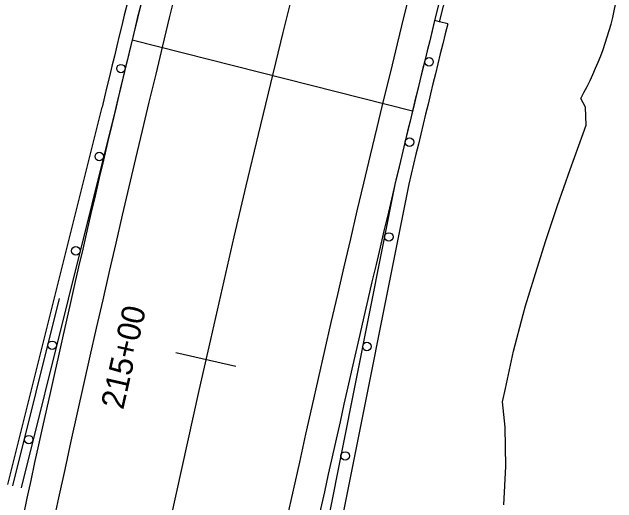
# Model space of a CAD drawing. Extents: x 1441466 to 1476381, y 2042742 to 2057194.
# Drawn here: x 1445767.1 to 1445924, y 2054420.2 to 2054547.4 of the extents above; entities that cross this region are included whole.
import ezdxf

# ---------------------------------------------------------------- set-up
doc = ezdxf.new("R2010")
doc.units = 0
for name, color, linetype in [('R_Bridge', 7, 'Continuous'), ('R_Guardrail', 7, 'Continuous'), ('R_Horz Alg', 7, 'Continuous'), ('R_Horz Alg Stationing', 7, 'Continuous'), ('R_Proposed Const Limits', 7, 'Continuous'), ('R_Proposed Road', 7, 'Continuous'), ('R_Shld', 7, 'Continuous')]:
    doc.layers.add(name, color=color, linetype=linetype)

msp = doc.modelspace()

# ---------------------------------------------------------------- linework, layer by layer
at = {"layer": 'R_Bridge'}
for p, q in [((1445877.91, 2054544.87), (1445876.7, 2054545.19)), ((1445870.95, 2054521.66), (1445798.24, 2054540.08))]:
    msp.add_line(p, q, dxfattribs=at)
for radius, start, end in [(5171.21, 164.64438, 166.12942), (5169.96, 164.6442, 166.1296)]:
    msp.add_arc((1450897.11, 2053305.5), radius, start, end, dxfattribs=at)
at = {"layer": 'R_Guardrail'}
for p, q in [((1445793.85, 2054521.9), (1445769.43, 2054424.06)), ((1445866.57, 2054503.5), (1445832.54, 2054333.21)), ((1445767.3, 2054424.59), (1445779.41, 2054473.1))]:
    msp.add_line(p, q, dxfattribs=at)
for centre in [(1445875.23, 2054534.47), (1445795.35, 2054532.72), (1445870.17, 2054513.65), (1445789.73, 2054509.93), (1445864.81, 2054489.09), (1445783.63, 2054485.47), (1445777.52, 2054461.01), (1445859.14, 2054460.71), (1445771.42, 2054436.55), (1445853.47, 2054432.33)]:
    msp.add_circle(centre, 1.1, dxfattribs=at)
for radius, start, end in [(5246.21, 166.09664, 166.57147), (5171.21, 166.10776, 166.58266)]:
    msp.add_arc((1450896.63, 2053303.56), radius, start, end, dxfattribs=at)
at = {"layer": 'R_Horz Alg'}
msp.add_arc((1450897.11, 2053305.5), 5208.71, 164.16667, 183.33333, dxfattribs=at)
at = {"layer": 'R_Horz Alg Stationing'}
msp.add_lwpolyline([(1445809.56, 2054459.13), (1445825.17, 2054455.59)], dxfattribs=at)
at = {"layer": 'R_Proposed Const Limits'}
for points in [[(1445915.98, 2054518.08), (1445915.84, 2054522.76), (1445914.56, 2054525)], [(1445894.66, 2054419.65), (1445895.14, 2054429.63), (1445894.96, 2054439.77), (1445894.32, 2054446.33), (1445895.06, 2054449.84), (1445897.1, 2054459.49), (1445899.61, 2054469.01), (1445900.26, 2054471.22), (1445902.52, 2054478.45), (1445905.46, 2054487.88), (1445908.53, 2054497.27), (1445911.86, 2054506.59), (1445915.2, 2054515.91), (1445915.98, 2054518.08)]]:
    msp.add_lwpolyline(points, dxfattribs=at)
msp.add_arc((1445842.36, 2054565.73), 82.9, 330.5724, 349.8164, dxfattribs=at)
at = {"layer": 'R_Proposed Road'}
for radius, start in [(5238.21, 164.16667), (5179.21, 164.16667), (5246.21, 166.11849), (5171.21, 166.12942)]:
    msp.add_arc((1450897.11, 2053305.5), radius, start, 169.4239, dxfattribs=at)
at = {"layer": 'R_Shld'}
for p, q in [((1445880.09, 2054544.31), (1445877.91, 2054544.87)), ((1445766.04, 2054424.9), (1445790.45, 2054522.73)), ((1445869.99, 2054502.75), (1445835.97, 2054332.52))]:
    msp.add_line(p, q, dxfattribs=at)
for radius, start, end in [(5249.71, 166.09615, 166.57127), (5167.71, 166.10776, 166.58194)]:
    msp.add_arc((1450896.63, 2053303.56), radius, start, end, dxfattribs=at)

# ---------------------------------------------------------------- texts
at = {"layer": 'R_Horz Alg Stationing'}
msp.add_text('215+00', height=6, rotation=77.2239, dxfattribs=at).set_placement((1445795.91, 2054444.13))

doc.saveas('drawing.dxf')
